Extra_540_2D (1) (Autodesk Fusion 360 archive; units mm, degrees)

design "Extra_540_2D" references "Propeller_2-5_x_1", "Motor_body", "Extra_540_wheel"
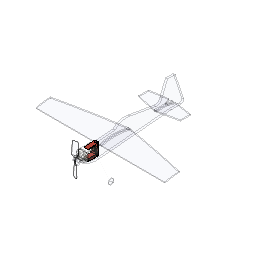
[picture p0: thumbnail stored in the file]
canvas "Canvas1"
canvas "Canvas2"
canvas "Canvas3"
component_insert "Component Insert1"
as_built_joint "As-built1"
component_insert "Component Insert2"
joint "Assemble2" OffsetX 0 OffsetY 0 OffsetZ 0 AngleZ 0 OffsetX 0 OffsetY 0 OffsetZ 0 AngleZ 0 alignAngle 0 alignOffsetX 0 alignOffsetY 0 alignOffsetZ 0
ground "Ground1"
canvas "Canvas1"
canvas "Canvas2"
canvas "Canvas3"
sketch "Sketch10" plane through (0, 0, 0) normal (1, 0, 0) x axis (0, 0, -1)
  dimension "d55" = 5
  dimension "d56" = 10.3443
extrude "Extrude4" new body sketch "Sketch10" distance 2 named "d24_1"
sketch "Sketch17" plane through (0, 0, 0) normal (1, 0, 0) x axis (0, 1, 0)
  dimension "d57" = 61
  dimension "d58" = 56
  dimension "d59" = 2
extrude "Extrude8" cut sketch "Sketch17" no distance stored
sketch "Sketch22" plane through (0, 0, 0) normal (1, 0, 0) x axis (0, 0, -1)
extrude "Extrude12" cut sketch "Sketch22" against normal blind 4 and along normal blind 4
ground "Ground2"
ground "Ground3"
sketch "Sketch1" plane through (0, 0, 0) normal (1, 0, 0) x axis (0, 0, -1)
extrude "Extrude1" new body sketch "Sketch1" distance 250
sketch "Sketch3" plane through (0, 0, 0) normal (0, 1, 0) x axis (1, 0, 0)
  dimension "d88" = 2.5
extrude "Extrude2" cut sketch "Sketch3" along normal blind 40 and against normal blind 40
ground "Ground4"
sketch "Sketch1" plane through (0, 0, 0) normal (1, 0, 0) x axis (0, 0, -1)
  dimension "d93" = 14
extrude "Extrude1" new body sketch "Sketch1" distance 8
sketch "Sketch5" plane through (0, 0, -47.8449) normal (0, 0, 1) x axis (1, 0, 0)
  dimension "d107" = 12
extrude "Extrude4" add sketch "Sketch5" to an object
sketch "Sketch2" plane through (2, 0, 0) normal (1, 0, 0) x axis (0, 0, -1)
  dimension "d96" = 4
extrude "Extrude2" add sketch "Sketch2" to an object
chamfer "Chamfer1" distance 1 distance 4
mirror "Mirror1"
sketch "Sketch3" plane through (0, 0, -47.8449) normal (0, 0, 1) x axis (1, 0, 0)
extrude "Extrude13" cut sketch "Sketch3" against normal blind 3
chamfer "Chamfer2" distance 0.9
sketch "Sketch7" plane through (4, 0, 0) normal (1, 0, 0) x axis (0, 0, -1)
  dimension "d113" = 0.6
extrude "Extrude5" cut sketch "Sketch7" no distance stored
sketch "Sketch8" plane through (4, 0, 0) normal (1, 0, 0) x axis (0, 0, -1)
  dimension "d115" = 3
extrude "Extrude6" add sketch "Sketch8" along normal blind 1.5
mirror "Mirror2"
work_plane "WorkPlane1" AlongDistance -49.2
sketch "Sketch1" plane through (0, 0, -49.2) normal (0, 0, 1) x axis (1, 0, 0)
  dimension "d120" = 0.75
  dimension "d121" = 4
  dimension "d130" = 0.5
  dimension "d131" = 1
  dimension "d132" = 0.5
  dimension "d133" = 0.5
  dimension "d134" = 1
work_plane "WorkPlane2" AlongDistance 35
sketch "Sketch2" plane through (35, 0, 0) normal (1, 0, 0) x axis (0, 0, -1)
  dimension "d136" = 0.5
sweep "Sweep2" sketch "Sketch2" TwistAngle 0 TaperAngle 0
ground "Ground5"
component_insert "Component Insert5"
joint "Assemble1" OffsetX 0 OffsetY 0 OffsetZ 0 AngleZ 0 alignAngle 0 alignOffsetX 0 alignOffsetY 0 alignOffsetZ -3
component_insert "Component Insert6"
joint "Assemble2" OffsetX 0 OffsetY 0 OffsetZ 0 AngleZ 0 alignAngle 0 alignOffsetX 0 alignOffsetY 0 alignOffsetZ -3
sketch "Sketch23" plane through (2, 0, 0) normal (1, 0, 0) x axis (0, 0, -1)
  dimension "d167" = 2
  dimension "d168" = 33
extrude "Extrude14" cut sketch "Sketch23" no distance stored
work_plane "WorkPlane1" AlongDistance 0
sketch "Sketch1" plane through (0, 2.9431, -184.0054) normal (0, 1, 0) x axis (1, 0, 0)
extrude "Extrude1" new body sketch "Sketch1" along normal blind 2
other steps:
extrude "Extrude3" cut sketch "Sketch3" against normal blind 3
create_component "CreateComponent2"
create_component "CreateComponent3"
create_component "CreateComponent4"
create_component "CreateComponent5"
create_component "CreateComponent6"
joint_origin "JointOrigin1" OffsetX 0 OffsetY 0 OffsetZ 0 AngleZ 0
joint_origin "JointOrigin2" OffsetX 0 OffsetY 0 OffsetZ 0 AngleZ 0
create_component "CreateComponent7"

design "Propeller_2-5_x_1"
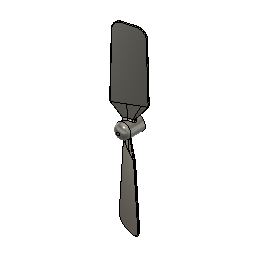
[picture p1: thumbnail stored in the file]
sketch "Sketch1" plane through (0, 0, 0) normal (1, 0, 0) x axis (0, 0, -1)
  dimension "d1" = 1
  dimension "d2" = 2.5
  dimension "d3" = 2
  dimension "d5" = 7
  dimension "d6" = 115
  dimension "d7" = 1.5
revolve "Revolve1" sketch "Sketch1" AlongAngle 360
work_plane "WorkPlane1" AlongDistance 31
sketch "Sketch2" plane through (0, 31, 0) normal (0, 1, 0) x axis (1, 0, 0)
  dimension "d10" = 3
  dimension "d11" = 10
  dimension "d12" = 0.5
  dimension "d13" = 10
work_plane "WorkPlane2" AlongDistance 7
sketch "Sketch3" plane through (0, 7, 0) normal (0, 1, 0) x axis (1, 0, 0)
  dimension "d15" = 10
  dimension "d16" = 0.5
  dimension "d17" = 30
sketch "Sketch4" plane through (0, 0, 0) normal (1, 0, 0) x axis (0, 0, -1)
sweep "Sweep1" sketch "Sketch3" TwistAngle -15 TaperAngle 0
sketch "Sketch5" plane through (0, 0, 0) normal (0, 1, 0) x axis (1, 0, 0)
  dimension "d24" = 0.5
  dimension "d25" = 1
  dimension "d26" = 60
sketch "Sketch6" plane through (0, 0, 0) normal (1, 0, 0) x axis (0, 0, -1)
loft "Loft2" sketch "Sketch5" + "Sketch3"
fillet "Fillet2" radius 3
fillet "Fillet3" radius 2
fillet "Fillet4" radius 0.2
fillet "Fillet5" radius 0.5
circular_pattern "C-Pattern1" TotalAngle 360

design "Extra_540_wheel"
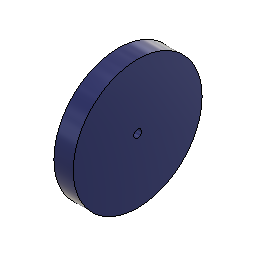
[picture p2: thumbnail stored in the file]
sketch "Sketch1" plane through (0, 0, 0) normal (1, 0, 0) x axis (0, 0, -1)
  circle C1 centre (0, 0) radius 0.3
  circle C2 centre (0, 0) radius 5
  dimension "d1" diameter C1 = 0.6
  dimension "d2" diameter C2 = 10
extrude "Extrude1" new body sketch "Sketch1" along normal blind 1.5

design "Motor_body"
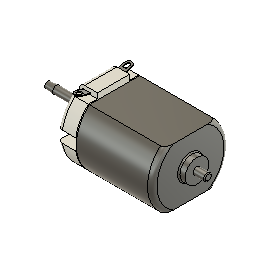
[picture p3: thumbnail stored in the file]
sketch "Sketch1" plane through (0, 0, 0) normal (1, 0, 0) x axis (0, 0, -1)
  dimension "d1" = 20.1
  dimension "d2" = 15.1
extrude "Extrude1" new body sketch "Sketch1" along normal blind 20
sketch "Sketch2" plane through (0, 0, 0) normal (-1, 0, 0) x axis (0, 0, 1)
  dimension "d5" = 1
extrude "Extrude2" add sketch "Sketch2" along normal blind 0.25
sketch "Sketch1"
sketch "Sketch2" plane through (0, 0, 0) normal (1, 0, 0) x axis (0, 0, -1)
work_plane "WorkPlane1"
sketch "Sketch3" plane through (-0.25, 6.55, 6.245) normal (1, 0, 0) x axis (0, 0, -1)
  dimension "d8" = 8.5
  dimension "d9" = 1.4
extrude "Extrude1" new body sketch "Sketch3" against normal blind 4.75
sketch "Sketch4" plane through (-5, 0, 0) normal (-1, 0, 0) x axis (0, 0, 1)
  dimension "d12" = 10
  dimension "d13" = 4
extrude "Extrude2" add sketch "Sketch4" along normal blind 2.3
sketch "Sketch3" plane through (20, 0, 0) normal (1, 0, 0) x axis (0, 0, -1)
  dimension "d16" = 6.15
extrude "Extrude3" add sketch "Sketch3" along normal blind 1.7
sketch "Sketch1" plane through (-7.3, 0, 0) normal (-1, 0, 0) x axis (0, 0, 1)
  dimension "d19" = 2
extrude "Extrude1" new body sketch "Sketch1" along normal blind 10.3
sketch "Sketch2" plane through (21.7, 0, 0) normal (1, 0, 0) x axis (0, 0, -1)
  circle C1 centre (0, 0) radius 3.075
extrude "Extrude4" cut of existing geometry blind -42.3
work_plane "WorkPlane1" AlongDistance 2
sketch "Sketch1" plane through (-2, 0, 0) normal (-1, 0, 0) x axis (0, 0, -1)
  dimension "d29" = 3.25
  dimension "d30" = 0.2
  dimension "d31" = 15
extrude "Extrude1" new body sketch "Sketch1" along normal blind 2
fillet "Fillet1" radius 1
sketch "Sketch2" plane through (0, 6.4116, 1.718) normal (0, 0.9659, 0.2588) x axis (1, 0, 0)
  dimension "d36" = 1.5
  dimension "d37" = 0.5
extrude "Extrude2" cut sketch "Sketch2" to an object
sketch "Sketch3" plane through (0, 6.4116, -1.718) normal (0, 0.9659, -0.2588) x axis (-1, 0, 0)
  dimension "d41" = 1.5
  dimension "d42" = 0.5
extrude "Extrude3" cut sketch "Sketch3" to an object
sketch "Sketch5" plane through (-5, 0, 0) normal (-1, 0, 0) x axis (0, 0, 1)
  dimension "d45" = 6
  dimension "d46" = 1
  dimension "d47" = 1
  dimension "d48" = 7
extrude "Extrude4" add sketch "Sketch5" along normal blind 0.1
sketch "Sketch6" plane through (-5, 0, 0) normal (-1, 0, 0) x axis (0, 0, 1)
  dimension "d51" = 3
  dimension "d52" = 4.825
extrude "Extrude5" cut sketch "Sketch6" to an object
chamfer "Chamfer1" distance 0.2 rotateAngle 85
fillet "Fillet1" radius 1.25
fillet "Fillet1" radius 1.25
extrude "Extrude3" add of existing geometry blind 32
chamfer "Chamfer1" distance 0.5 rotateAngle 45
fillet "Fillet2" radius 1.4
fillet "Fillet2" radius 0.3
fillet "Fillet1" radius 0.25
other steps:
create_component "CreateComponent1"
create_component "CreateComponent2"
extrude "Extrude3" cut of existing geometry blind -42.3
extrude "Extrude2" cut of existing geometry blind -42.3
create_component "CreateComponent3"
